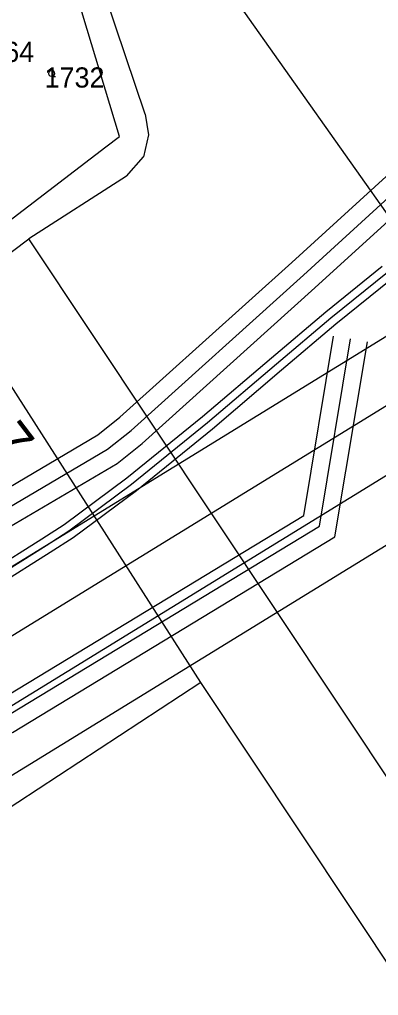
# Model space of a CAD drawing. Extents: x -510185 to -506993, y -1126306 to -1123642.
# Drawn here: x -508152.3 to -508061.6, y -1124075.2 to -1123828.7 of the extents above; entities that cross this region are included whole.
import ezdxf

# ---------------------------------------------------------------- set-up
doc = ezdxf.new("R2010")
doc.units = 0
for name, color, linetype in [('Net4gas', 7, 'Continuous'), ('parcelni hranice', 7, 'Continuous'), ('popis cesty', 7, 'Continuous'), ('u_kabely', 7, 'Continuous'), ('u_net4gas', 7, 'Continuous'), ('u_sitel_self_net4', 7, 'Continuous'), ('u_ČEZ nadzemní VVN 110', 7, 'Continuous'), ('ČEZ', 7, 'Continuous'), ('ˇ2', 7, 'Continuous'), ('ˇ3', 7, 'Continuous')]:
    doc.layers.add(name, color=color, linetype=linetype)

msp = doc.modelspace()

# ---------------------------------------------------------------- linework, layer by layer
at = {"layer": 'Net4gas'}
for points in [[(-508209.34, -1123978.83), (-508159.28, -1123949.34), (-508132.58, -1123933.61), (-508126.96, -1123929.15), (-508083.48, -1123890.01), (-508045.36, -1123855.26), (-508012.03, -1123825.37), (-507981.75, -1123798.69), (-507943.8, -1123765.47), (-507913.54, -1123739.15), (-507890, -1123718.31)], [(-508198.87, -1123982.75), (-508154.86, -1123956.84), (-508127.64, -1123940.8), (-508121.34, -1123935.8), (-508077.64, -1123896.45), (-508039.53, -1123861.72), (-508006.25, -1123831.88), (-507976.01, -1123805.23), (-507938.08, -1123772.03), (-507907.8, -1123745.69), (-507890, -1123729.93)], [(-509848.66, -1125447.37), (-509847.51, -1125434.96), (-509799.55, -1125382.98), (-509798.81, -1124945.67), (-509798.75, -1124907.97), (-508222.29, -1123973.97), (-508155.01, -1123999.2), (-508080.5, -1123953.99), (-508072.94, -1123908.62)], [(-508208.52, -1123988.43), (-508154.11, -1124008.83), (-508072.58, -1123959.36), (-508064.36, -1123910.05)]]:
    msp.add_lwpolyline(points, dxfattribs=at)
at = {"layer": 'parcelni hranice'}
for p, q in [((-508138.29, -1123766.29), (-508025.21, -1123926.21)), ((-508127.04, -1123858.18), (-508151.25, -1123778.3)), ((-508120.55, -1123852.55), (-508136.73, -1123804.83)), ((-508120.55, -1123852.55), (-508119.71, -1123857.75)), ((-508130.51, -1123860.84), (-508127.04, -1123858.18)), ((-508119.71, -1123857.75), (-508120.97, -1123863.38)), ((-508176.54, -1123896.06), (-508130.51, -1123860.84)), ((-508125.33, -1123868.27), (-508120.97, -1123863.38)), ((-508125.33, -1123868.27), (-508149.98, -1123884.08)), ((-508169.14, -1123898.35), (-508149.98, -1123884.08)), ((-508051.07, -1124032.72), (-508149.98, -1123884.08)), ((-508106.47, -1123996.19), (-508169.14, -1123898.35)), ((-508106.47, -1123996.19), (-508212.87, -1124065.79)), ((-508045.74, -1124087.56), (-508106.47, -1123996.19))]:
    msp.add_line(p, q, dxfattribs=at)
at = {"layer": 'u_kabely'}
for points in [[(-508159.88, -1123968.08), (-508146.71, -1123959.87), (-508141.02, -1123956.21), (-508125.24, -1123944.47), (-508106.08, -1123928.97), (-508088.67, -1123914.15), (-508074.88, -1123902.47), (-508060.62, -1123890.98)], [(-508157.76, -1123971.46), (-508144.57, -1123963.25), (-508138.74, -1123959.51), (-508122.78, -1123947.63), (-508103.52, -1123932.05), (-508086.09, -1123917.19), (-508072.34, -1123905.55), (-508058.06, -1123894.04)]]:
    msp.add_lwpolyline(points, dxfattribs=at)
at = {"layer": 'u_net4gas'}
for points in [[(-508251.72, -1124009.37), (-508251.34, -1124009.14), (-508211.3, -1123985.03), (-508157.07, -1123953.09), (-508130.11, -1123937.2), (-508124.15, -1123932.47), (-508080.56, -1123893.23), (-508042.45, -1123858.49), (-508009.14, -1123828.62), (-507978.88, -1123801.96), (-507940.94, -1123768.75), (-507910.72, -1123742.46)], [(-509843.66, -1125437.1), (-509795.2, -1125384.69), (-509794.46, -1124945.67), (-509794.41, -1124910.45), (-508221.87, -1123978.78), (-508154.56, -1124004.01), (-508076.54, -1123956.67), (-508068.65, -1123909.34)]]:
    msp.add_lwpolyline(points, dxfattribs=at)
at = {"layer": 'u_sitel_self_net4'}
msp.add_lwpolyline([(-508158.82, -1123969.77), (-508145.64, -1123961.56), (-508139.88, -1123957.86), (-508124.01, -1123946.05), (-508104.8, -1123930.51), (-508087.38, -1123915.67), (-508073.61, -1123904.01), (-508059.34, -1123892.51)], dxfattribs=at)
msp.add_lwpolyline([(-508158.82, -1123969.77), (-508145.64, -1123961.56), (-508139.88, -1123957.86), (-508124.01, -1123946.05), (-508104.8, -1123930.51), (-508087.38, -1123915.67), (-508073.61, -1123904.01), (-508059.34, -1123892.51)], dxfattribs=at)
msp.add_lwpolyline([(-508158.82, -1123969.77), (-508145.64, -1123961.56), (-508139.88, -1123957.86), (-508124.01, -1123946.05), (-508104.8, -1123930.51), (-508087.38, -1123915.67), (-508073.61, -1123904.01), (-508059.34, -1123892.51)], dxfattribs=at)
at = {"layer": 'u_ČEZ nadzemní VVN 110'}
for points in [[(-510185.05, -1125088.12), (-510078.46, -1125047.86), (-509826.19, -1124952), (-509610.8, -1124868.87), (-509433.8, -1124763.7), (-509229.42, -1124638.63), (-509031.49, -1124517.69), (-508838.02, -1124402.59), (-508649.38, -1124285.61), (-508435.7, -1124156.49), (-508228.65, -1124030.06), (-508022.78, -1123903.6), (-507910.72, -1123835.24)], [(-510185.05, -1125104.16), (-510073.15, -1125061.88), (-509820.83, -1124966.01), (-509604.22, -1124882.41), (-509426.06, -1124776.54), (-509221.59, -1124651.43), (-509023.75, -1124530.54), (-508830.23, -1124415.41), (-508641.55, -1124298.4), (-508427.91, -1124169.31), (-508220.82, -1124042.85), (-508014.95, -1123916.4), (-507910.72, -1123852.81)]]:
    msp.add_lwpolyline(points, dxfattribs=at)
at = {"layer": 'ČEZ'}
for points in [[(-510185.05, -1125072.09), (-510083.78, -1125033.83), (-509831.56, -1124937.99), (-509617.38, -1124855.33), (-509441.55, -1124750.85), (-509237.24, -1124625.83), (-509039.24, -1124504.85), (-508845.81, -1124389.77), (-508657.21, -1124272.81), (-508443.48, -1124143.67), (-508236.48, -1124017.27), (-508030.61, -1123890.81), (-507890, -1123805.03)], [(-510185.05, -1125120.19), (-510067.83, -1125075.91), (-509815.46, -1124980.02), (-509597.65, -1124895.95), (-509418.31, -1124789.39), (-509213.77, -1124664.22), (-509016, -1124543.38), (-508822.44, -1124428.23), (-508633.72, -1124311.19), (-508420.12, -1124182.13), (-508212.98, -1124055.65), (-508007.12, -1123929.19), (-507890, -1123857.74)]]:
    msp.add_lwpolyline(points, dxfattribs=at)
at = {"layer": 'ˇ3'}
msp.add_lwpolyline([(-508144.21, -1123843.05), (-508144.59, -1123842.95), (-508144.86, -1123842.68), (-508144.96, -1123842.3), (-508144.86, -1123841.93), (-508144.59, -1123841.65), (-508144.21, -1123841.55), (-508143.84, -1123841.65), (-508143.56, -1123841.93), (-508143.46, -1123842.3), (-508143.56, -1123842.68), (-508143.84, -1123842.95), (-508144.21, -1123843.05), (-508143.21, -1123843.05)], dxfattribs=at)

# ---------------------------------------------------------------- texts
at = {"layer": 'popis cesty'}
msp.add_text('KÚ-km 0,117', height=10, rotation=307.4004, dxfattribs=at).set_placement((-508203.4, -1123879.13))
at = {"layer": 'ˇ2'}
for s, p in [('1264', (-508163.8, -1123839.38)), ('1732', (-508146.02, -1123845.85))]:
    msp.add_text(s, height=5.1, dxfattribs=at).set_placement(p)

doc.saveas('drawing.dxf')
